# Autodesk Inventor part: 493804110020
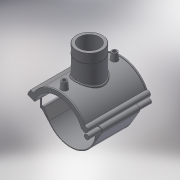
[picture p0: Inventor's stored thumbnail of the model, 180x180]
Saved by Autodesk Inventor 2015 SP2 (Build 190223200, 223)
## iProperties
Created: 2017-07
Part Number: 493804110020
Material: Generic
Description: PLASSON TRANSITION SADDLE 110-2"
Document SubType Name: Modeling
Designer: KIM
Density: 1 g/cm^3
Appearance: Default
Author: KIM
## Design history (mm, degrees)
derived "493804.ipt"
feature "Solid1::493804.ipt"
tag "TaggingFeature1"
body "Solid1"
other parameters: "B_" = 158, "H_" = 76, "L_" = 176, "d_t" = 6, "G_" = 56.656, "d148" = 1.65, "d160" = 1.65, "d169" = 1.65, "d192" = 3.96, "d1" = 129.8, "d2" = 158, "d3" = 27.5, "d4" = 176, "d5" = 0, "d6" = 0.1, "d8" = 0, "d19" = 6, "d20" = 6, "d21" = 105.6, "d23" = 0, "d24" = 52.8, "d26" = 0, "d27" = 3, "d28" = 3, "d29" = 3, "d30" = 36.66667, "d31" = 6, "d32" = 0, "d33" = 0, "d34" = 0.6, "d40" = 67.496, "d41" = 79.3184, "d43" = 0, "d45" = 0, "d47" = 140.9, "d48" = 73.6528, "d50" = 0, "d70" = 15, "d72" = 0, "d73" = 6, "d75" = 5, "d76" = 0, "d77" = 5.5, "d78" = 85, "d79" = 15, "d80" = 70.4, "d82" = 5 deg, "d84" = 4, "d85" = 14, "d86" = 0, "d87" = 3, "d88" = 0, "d89" = 1, "d90" = 1, "d91" = 140.8, "d92" = 0, "d93" = 0.5, "d94" = 57.89474, "d96" = 132.396, "d97" = 3.52, "d98" = 0, "d102" = 1.69968, "d103" = 56.656, "d104" = 45.6, "d105" = 0, "d106" = 45.3248, "d108" = 0, "d109" = -25.33333, "d111" = 0.5, "d112" = 0.5, "d113" = 0, "d114" = 0.5, "d117" = 0.56656, "d120" = 140 deg, "d121" = 24.228, "d122" = 20 deg, "d123" = 259.6, "d124" = 77.88, "d126" = 0, "d143" = 113.3, "d145" = 15.23077, "d149" = 1.65, "d150" = 16.75385, "d153" = 176, "d154" = 0, "d156" = 64.9, "d157" = 160 deg, "d159" = 3.96, "d161" = 1.65, "d162" = 105.6, "d163" = 0, "d164" = 55, "d167" = 11, "d168" = 63.31707, "d170" = 1.65, "d172" = 0, "d173" = 1, "d175" = 55, "d176" = 20 deg, "d177" = 7.7, "d178" = 19.8, "d180" = 0, "d183" = 7.92, "d184" = 6.16, "d185" = 57.2, "d186" = 57.2, "d187" = 64.9, "d188" = 5.94, "d189" = 7.7, "d190" = 0, "d191" = 77.88, "d193" = 3.96, "d194" = 4.4, "d195" = 90 deg, "d197" = 0, "d199" = 0
